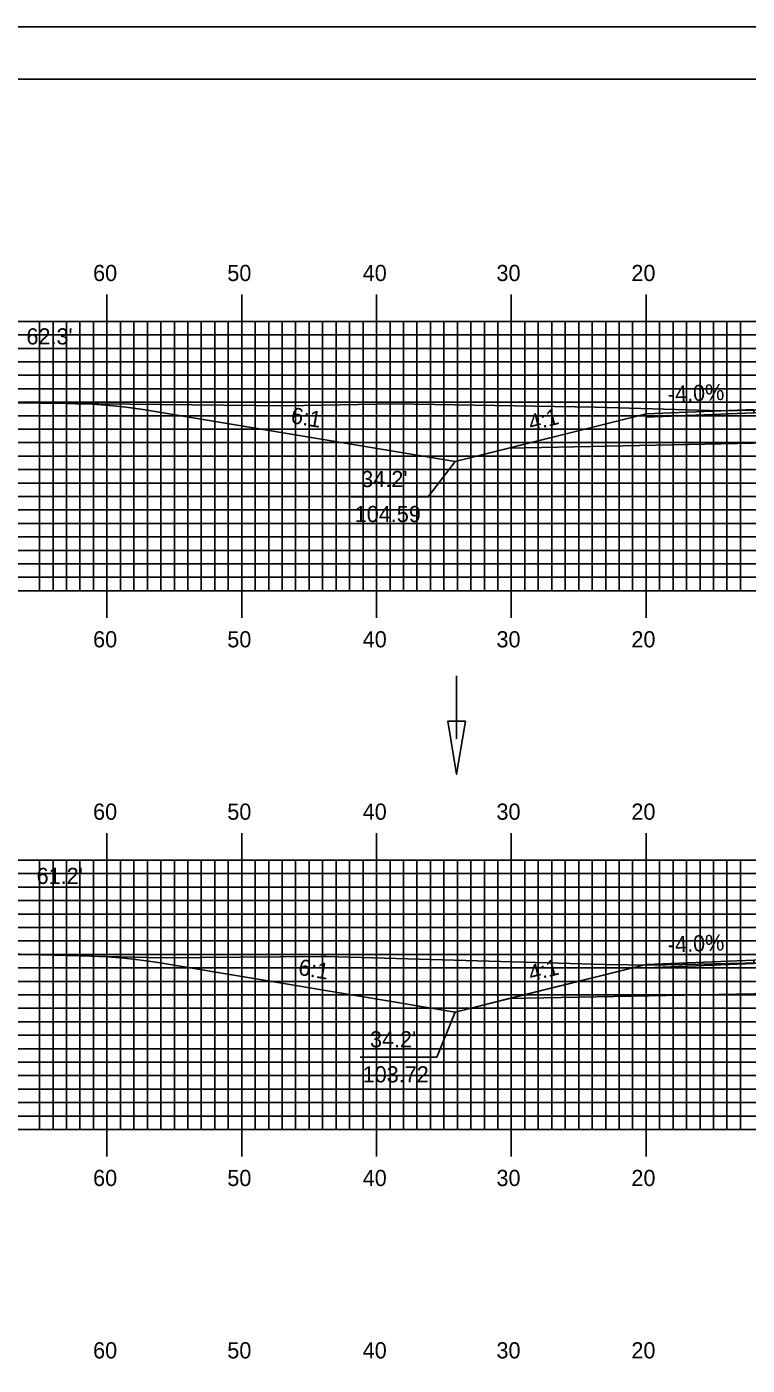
# Model space of a CAD drawing. Extents: x 1779106 to 1779449, y 442591 to 442811.
# Drawn here: x 1779205.4 to 1779258.8, y 442711.2 to 442810.5 of the extents above; entities that cross this region are included whole.
import ezdxf

# ---------------------------------------------------------------- set-up
doc = ezdxf.new("R2010")
doc.units = 0
for name, color, linetype in [('ANNOTATION', 7, 'Continuous'), ('BORDER', 7, 'Continuous'), ('D_Drainage_Ditch_Line', 7, 'Continuous'), ('D_Roadway_Centerline', 7, 'Continuous'), ('D_Roadway_Edge_Shoulder', 7, 'Continuous'), ('D_Roadway_SlopeLines', 7, 'Continuous'), ('D_Roadway_SubGrade', 7, 'Continuous'), ('D_Text_Standard', 7, 'Continuous'), ('H_V ANNOTATION', 7, 'Continuous'), ('MAJOR', 7, 'Continuous'), ('MINOR', 7, 'Continuous'), ('PLOT BOUNDARY', 7, 'Continuous'), ('S_Roadway_Centerline', 7, 'Continuous')]:
    doc.layers.add(name, color=color, linetype=linetype)

msp = doc.modelspace()

# ---------------------------------------------------------------- linework, layer by layer
at = {"layer": 'ANNOTATION'}
for points in [[(1779229.461, 442775.639), (1779235.153, 442775.639), (1779237.155, 442778.259)], [(1779230.108, 442734.035), (1779235.8, 442734.035), (1779237.155, 442737.384)]]:
    msp.add_lwpolyline(points, dxfattribs=at)
at = {"layer": 'BORDER'}
msp.add_lwpolyline([(1779121.729, 442596.665), (1779441.729, 442596.665), (1779441.729, 442806.665), (1779121.729, 442806.665)], close=True, dxfattribs=at)
at = {"layer": 'D_Drainage_Ditch_Line'}
msp.add_line((1779237.267, 442757.661), (1779237.267, 442762.36), dxfattribs=at)
msp.add_lwpolyline([(1779237.924, 442758.974), (1779236.611, 442758.974), (1779237.267, 442755.037)], close=True, dxfattribs=at)
at = {"layer": 'D_Roadway_Centerline'}
for points in [[(1779209.014, 442782.559), (1779210.264, 442782.521), (1779210.312, 442782.518), (1779211.513, 442782.435), (1779212.323, 442782.348), (1779212.764, 442782.3), (1779213.418, 442782.204), (1779214.014, 442782.116), (1779237.153, 442778.26), (1779237.155, 442778.259), (1779241.155, 442779.259), (1779251.329, 442781.802), (1779259.33, 442782.122)], [(1779210.128, 442741.537), (1779211.378, 442741.483), (1779212.589, 442741.387), (1779212.628, 442741.384), (1779212.654, 442741.381), (1779213.879, 442741.241), (1779215.128, 442741.055), (1779237.155, 442737.384), (1779241.156, 442738.384), (1779251.329, 442740.927), (1779259.329, 442741.247), (1779271.328, 442741.487), (1779271.329, 442741.487), (1779278.201, 442741.35), (1779283.329, 442741.247), (1779293.329, 442740.847), (1779303.329, 442738.348), (1779307.184, 442737.384)]]:
    msp.add_lwpolyline(points, dxfattribs=at)
at = {"layer": 'D_Roadway_Edge_Shoulder'}
for points in [[(1779259.33, 442782.122), (1779251.329, 442781.802), (1779251.329, 442781.552), (1779259.33, 442781.872)], [(1779259.329, 442741.247), (1779251.329, 442740.927), (1779251.329, 442740.677), (1779259.329, 442740.997)]]:
    msp.add_lwpolyline(points, close=True, dxfattribs=at)
at = {"layer": 'D_Roadway_SlopeLines'}
for points in [[(1779237.155, 442778.259), (1779214.014, 442782.116), (1779212.764, 442782.3), (1779211.513, 442782.435), (1779210.264, 442782.521), (1779209.014, 442782.559)], [(1779251.329, 442781.802), (1779237.155, 442778.259)], [(1779237.155, 442737.384), (1779215.128, 442741.055), (1779213.879, 442741.241), (1779212.628, 442741.384), (1779211.378, 442741.483), (1779210.128, 442741.537)], [(1779251.329, 442740.927), (1779237.155, 442737.384)]]:
    msp.add_lwpolyline(points, dxfattribs=at)
at = {"layer": 'D_Roadway_SubGrade'}
for points in [[(1779259.33, 442779.622), (1779241.155, 442779.259), (1779251.329, 442781.802), (1779251.329, 442781.552), (1779259.33, 442781.872), (1779271.329, 442782.112), (1779283.329, 442781.872), (1779291.329, 442781.552), (1779291.329, 442781.802), (1779301.503, 442779.259), (1779283.329, 442779.622), (1779271.329, 442779.862)], [(1779259.329, 442738.747), (1779241.156, 442738.384), (1779251.329, 442740.927), (1779251.329, 442740.677), (1779259.329, 442740.997), (1779271.329, 442741.237), (1779283.329, 442740.997), (1779293.329, 442740.597), (1779293.329, 442740.847), (1779303.329, 442738.348), (1779283.329, 442738.747), (1779271.329, 442738.987)]]:
    msp.add_lwpolyline(points, close=True, dxfattribs=at)
at = {"layer": 'MAJOR'}
for p, q in [((1779211.329, 442790.669), (1779211.329, 442788.665)), ((1779221.329, 442790.669), (1779221.329, 442788.665)), ((1779231.329, 442790.669), (1779231.329, 442788.665)), ((1779241.329, 442790.669), (1779241.329, 442788.665)), ((1779251.329, 442790.669), (1779251.329, 442788.665)), ((1779131.329, 442788.665), (1779411.329, 442788.665)), ((1779131.329, 442788.665), (1779411.329, 442788.665)), ((1779211.329, 442768.665), (1779211.329, 442788.665)), ((1779221.329, 442768.665), (1779221.329, 442788.665)), ((1779231.329, 442768.665), (1779231.329, 442788.665)), ((1779241.329, 442768.665), (1779241.329, 442788.665)), ((1779251.329, 442768.665), (1779251.329, 442788.665)), ((1779131.329, 442783.665), (1779411.329, 442783.665)), ((1779131.329, 442778.665), (1779411.329, 442778.665)), ((1779131.329, 442773.665), (1779411.329, 442773.665)), ((1779131.329, 442768.665), (1779411.329, 442768.665)), ((1779131.329, 442768.665), (1779411.329, 442768.665)), ((1779211.329, 442766.661), (1779211.329, 442768.665)), ((1779221.329, 442766.661), (1779221.329, 442768.665)), ((1779231.329, 442766.661), (1779231.329, 442768.665)), ((1779241.329, 442766.661), (1779241.329, 442768.665)), ((1779251.329, 442766.661), (1779251.329, 442768.665)), ((1779211.329, 442750.669), (1779211.329, 442748.665)), ((1779221.329, 442750.669), (1779221.329, 442748.665)), ((1779231.329, 442750.669), (1779231.329, 442748.665)), ((1779241.329, 442750.669), (1779241.329, 442748.665)), ((1779251.329, 442750.669), (1779251.329, 442748.665)), ((1779131.329, 442748.665), (1779411.329, 442748.665)), ((1779131.329, 442748.665), (1779411.329, 442748.665)), ((1779211.329, 442728.665), (1779211.329, 442748.665)), ((1779221.329, 442728.665), (1779221.329, 442748.665)), ((1779231.329, 442728.665), (1779231.329, 442748.665)), ((1779241.329, 442728.665), (1779241.329, 442748.665)), ((1779251.329, 442728.665), (1779251.329, 442748.665)), ((1779131.329, 442743.665), (1779411.329, 442743.665)), ((1779131.329, 442738.665), (1779411.329, 442738.665)), ((1779131.329, 442733.665), (1779411.329, 442733.665)), ((1779131.329, 442728.665), (1779411.329, 442728.665)), ((1779131.329, 442728.665), (1779411.329, 442728.665)), ((1779211.329, 442726.661), (1779211.329, 442728.665)), ((1779221.329, 442726.661), (1779221.329, 442728.665)), ((1779231.329, 442726.661), (1779231.329, 442728.665)), ((1779241.329, 442726.661), (1779241.329, 442728.665)), ((1779251.329, 442726.661), (1779251.329, 442728.665))]:
    msp.add_line(p, q, dxfattribs=at)
at = {"layer": 'MINOR'}
for p, q in [((1779206.329, 442768.665), (1779206.329, 442788.665)), ((1779207.329, 442768.665), (1779207.329, 442788.665)), ((1779208.329, 442768.665), (1779208.329, 442788.665)), ((1779209.329, 442768.665), (1779209.329, 442788.665)), ((1779210.329, 442768.665), (1779210.329, 442788.665)), ((1779212.329, 442768.665), (1779212.329, 442788.665)), ((1779213.329, 442768.665), (1779213.329, 442788.665)), ((1779214.329, 442768.665), (1779214.329, 442788.665)), ((1779215.329, 442768.665), (1779215.329, 442788.665)), ((1779216.329, 442768.665), (1779216.329, 442788.665)), ((1779217.329, 442768.665), (1779217.329, 442788.665)), ((1779218.329, 442768.665), (1779218.329, 442788.665)), ((1779219.329, 442768.665), (1779219.329, 442788.665)), ((1779220.329, 442768.665), (1779220.329, 442788.665)), ((1779222.329, 442768.665), (1779222.329, 442788.665)), ((1779223.329, 442768.665), (1779223.329, 442788.665)), ((1779224.329, 442768.665), (1779224.329, 442788.665)), ((1779225.329, 442768.665), (1779225.329, 442788.665)), ((1779226.329, 442768.665), (1779226.329, 442788.665)), ((1779227.329, 442768.665), (1779227.329, 442788.665)), ((1779228.329, 442768.665), (1779228.329, 442788.665)), ((1779229.329, 442768.665), (1779229.329, 442788.665)), ((1779230.329, 442768.665), (1779230.329, 442788.665)), ((1779232.329, 442768.665), (1779232.329, 442788.665)), ((1779233.329, 442768.665), (1779233.329, 442788.665)), ((1779234.329, 442768.665), (1779234.329, 442788.665)), ((1779235.329, 442768.665), (1779235.329, 442788.665)), ((1779236.329, 442768.665), (1779236.329, 442788.665)), ((1779237.329, 442768.665), (1779237.329, 442788.665)), ((1779238.329, 442768.665), (1779238.329, 442788.665)), ((1779239.329, 442768.665), (1779239.329, 442788.665)), ((1779240.329, 442768.665), (1779240.329, 442788.665)), ((1779242.329, 442768.665), (1779242.329, 442788.665)), ((1779243.329, 442768.665), (1779243.329, 442788.665)), ((1779244.329, 442768.665), (1779244.329, 442788.665)), ((1779245.329, 442768.665), (1779245.329, 442788.665)), ((1779246.329, 442768.665), (1779246.329, 442788.665)), ((1779247.329, 442768.665), (1779247.329, 442788.665)), ((1779248.329, 442768.665), (1779248.329, 442788.665)), ((1779249.329, 442768.665), (1779249.329, 442788.665)), ((1779250.329, 442768.665), (1779250.329, 442788.665)), ((1779252.329, 442768.665), (1779252.329, 442788.665)), ((1779253.329, 442768.665), (1779253.329, 442788.665)), ((1779254.329, 442768.665), (1779254.329, 442788.665)), ((1779255.329, 442768.665), (1779255.329, 442788.665)), ((1779256.329, 442768.665), (1779256.329, 442788.665)), ((1779257.329, 442768.665), (1779257.329, 442788.665)), ((1779258.329, 442768.665), (1779258.329, 442788.665)), ((1779131.329, 442787.665), (1779411.329, 442787.665)), ((1779131.329, 442786.665), (1779411.329, 442786.665)), ((1779131.329, 442785.665), (1779411.329, 442785.665)), ((1779131.329, 442784.665), (1779411.329, 442784.665)), ((1779131.329, 442782.665), (1779411.329, 442782.665)), ((1779131.329, 442781.665), (1779411.329, 442781.665)), ((1779131.329, 442780.665), (1779411.329, 442780.665)), ((1779131.329, 442779.665), (1779411.329, 442779.665)), ((1779131.329, 442777.665), (1779411.329, 442777.665)), ((1779131.329, 442776.665), (1779411.329, 442776.665)), ((1779131.329, 442775.665), (1779411.329, 442775.665)), ((1779131.329, 442774.665), (1779411.329, 442774.665)), ((1779131.329, 442772.665), (1779411.329, 442772.665)), ((1779131.329, 442771.665), (1779411.329, 442771.665)), ((1779131.329, 442770.665), (1779411.329, 442770.665)), ((1779131.329, 442769.665), (1779411.329, 442769.665)), ((1779206.329, 442728.665), (1779206.329, 442748.665)), ((1779207.329, 442728.665), (1779207.329, 442748.665)), ((1779208.329, 442728.665), (1779208.329, 442748.665)), ((1779209.329, 442728.665), (1779209.329, 442748.665)), ((1779210.329, 442728.665), (1779210.329, 442748.665)), ((1779212.329, 442728.665), (1779212.329, 442748.665)), ((1779213.329, 442728.665), (1779213.329, 442748.665)), ((1779214.329, 442728.665), (1779214.329, 442748.665)), ((1779215.329, 442728.665), (1779215.329, 442748.665)), ((1779216.329, 442728.665), (1779216.329, 442748.665)), ((1779217.329, 442728.665), (1779217.329, 442748.665)), ((1779218.329, 442728.665), (1779218.329, 442748.665)), ((1779219.329, 442728.665), (1779219.329, 442748.665)), ((1779220.329, 442728.665), (1779220.329, 442748.665)), ((1779222.329, 442728.665), (1779222.329, 442748.665)), ((1779223.329, 442728.665), (1779223.329, 442748.665)), ((1779224.329, 442728.665), (1779224.329, 442748.665)), ((1779225.329, 442728.665), (1779225.329, 442748.665)), ((1779226.329, 442728.665), (1779226.329, 442748.665)), ((1779227.329, 442728.665), (1779227.329, 442748.665)), ((1779228.329, 442728.665), (1779228.329, 442748.665)), ((1779229.329, 442728.665), (1779229.329, 442748.665)), ((1779230.329, 442728.665), (1779230.329, 442748.665)), ((1779232.329, 442728.665), (1779232.329, 442748.665)), ((1779233.329, 442728.665), (1779233.329, 442748.665)), ((1779234.329, 442728.665), (1779234.329, 442748.665)), ((1779235.329, 442728.665), (1779235.329, 442748.665)), ((1779236.329, 442728.665), (1779236.329, 442748.665)), ((1779237.329, 442728.665), (1779237.329, 442748.665)), ((1779238.329, 442728.665), (1779238.329, 442748.665)), ((1779239.329, 442728.665), (1779239.329, 442748.665)), ((1779240.329, 442728.665), (1779240.329, 442748.665)), ((1779242.329, 442728.665), (1779242.329, 442748.665)), ((1779243.329, 442728.665), (1779243.329, 442748.665)), ((1779244.329, 442728.665), (1779244.329, 442748.665)), ((1779245.329, 442728.665), (1779245.329, 442748.665)), ((1779246.329, 442728.665), (1779246.329, 442748.665)), ((1779247.329, 442728.665), (1779247.329, 442748.665)), ((1779248.329, 442728.665), (1779248.329, 442748.665)), ((1779249.329, 442728.665), (1779249.329, 442748.665)), ((1779250.329, 442728.665), (1779250.329, 442748.665)), ((1779252.329, 442728.665), (1779252.329, 442748.665)), ((1779253.329, 442728.665), (1779253.329, 442748.665)), ((1779254.329, 442728.665), (1779254.329, 442748.665)), ((1779255.329, 442728.665), (1779255.329, 442748.665)), ((1779256.329, 442728.665), (1779256.329, 442748.665)), ((1779257.329, 442728.665), (1779257.329, 442748.665)), ((1779258.329, 442728.665), (1779258.329, 442748.665)), ((1779131.329, 442747.665), (1779411.329, 442747.665)), ((1779131.329, 442746.665), (1779411.329, 442746.665)), ((1779131.329, 442745.665), (1779411.329, 442745.665)), ((1779131.329, 442744.665), (1779411.329, 442744.665)), ((1779131.329, 442742.665), (1779411.329, 442742.665)), ((1779131.329, 442741.665), (1779411.329, 442741.665)), ((1779131.329, 442740.665), (1779411.329, 442740.665)), ((1779131.329, 442739.665), (1779411.329, 442739.665)), ((1779131.329, 442737.665), (1779411.329, 442737.665)), ((1779131.329, 442736.665), (1779411.329, 442736.665)), ((1779131.329, 442735.665), (1779411.329, 442735.665)), ((1779131.329, 442734.665), (1779411.329, 442734.665)), ((1779131.329, 442732.665), (1779411.329, 442732.665)), ((1779131.329, 442731.665), (1779411.329, 442731.665)), ((1779131.329, 442730.665), (1779411.329, 442730.665)), ((1779131.329, 442729.665), (1779411.329, 442729.665))]:
    msp.add_line(p, q, dxfattribs=at)
at = {"layer": 'PLOT BOUNDARY'}
msp.add_lwpolyline([(1779105.542, 442590.547), (1779445.542, 442590.547), (1779445.542, 442810.547), (1779105.542, 442810.547)], close=True, dxfattribs=at)
at = {"layer": 'S_Roadway_Centerline'}
for points in [[(1779204.323, 442782.626), (1779208.379, 442782.565), (1779224.594, 442782.397), (1779232.647, 442782.554), (1779247.552, 442782.307), (1779256.889, 442782.027), (1779269.461, 442782.27), (1779279.535, 442782.073), (1779285.297, 442781.72), (1779290.781, 442781.564), (1779304.666, 442781.605), (1779309.156, 442781.709), (1779314.679, 442781.638), (1779321.178, 442781.598), (1779327.747, 442781.551), (1779336.863, 442781.816)], [(1779203.403, 442741.748), (1779205.429, 442741.661), (1779215.254, 442741.403), (1779227.205, 442741.499), (1779227.424, 442741.508), (1779227.624, 442741.505), (1779248.292, 442740.919), (1779251.636, 442740.867), (1779261.056, 442741.059), (1779270.858, 442740.865), (1779273.556, 442740.862), (1779276.254, 442740.833), (1779285.251, 442740.863), (1779294.223, 442740.845), (1779299.806, 442740.668), (1779307.59, 442740.221), (1779317.29, 442740.535), (1779320.153, 442740.619), (1779322.749, 442740.624), (1779342.777, 442739.919)]]:
    msp.add_lwpolyline(points, dxfattribs=at)

# ---------------------------------------------------------------- texts
at = {"layer": 'ANNOTATION'}
for s, rotation, p in [('-4.0%', 2.29053, (1779252.961, 442782.669)), ('6:1', 350.53748, (1779224.917, 442781.127)), ('4:1', 14.03404, (1779242.778, 442780.526)), ('-4.0%', 2.29053, (1779252.961, 442741.794)), ('6:1', 350.538, (1779225.475, 442740.158)), ('4:1', 14.03473, (1779242.778, 442739.651))]:
    msp.add_text(s, height=1.2, rotation=rotation, dxfattribs=at).set_placement(p)
for s, p in [("34.2'", (1779230.196, 442776.365)), ('104.59', (1779229.709, 442773.765)), ("34.2'", (1779230.843, 442734.761)), ('103.72', (1779230.297, 442732.161))]:
    msp.add_text(s, height=1.2, dxfattribs=at).set_placement(p)
at = {"layer": 'D_Text_Standard'}
for s, p in [("62.3'", (1779205.355, 442786.956)), ("61.2'", (1779206.11, 442746.895))]:
    msp.add_text(s, height=1.2, dxfattribs=at).set_placement(p)
at = {"layer": 'H_V ANNOTATION'}
for s, p in [('60', (1779210.301, 442791.665)), ('50', (1779220.258, 442791.665)), ('40', (1779230.301, 442791.665)), ('30', (1779240.227, 442791.665)), ('20', (1779250.237, 442791.665)), ('60', (1779210.301, 442764.465)), ('50', (1779220.258, 442764.465)), ('40', (1779230.301, 442764.465)), ('30', (1779240.227, 442764.465)), ('20', (1779250.237, 442764.465)), ('60', (1779210.301, 442751.665)), ('50', (1779220.258, 442751.665)), ('40', (1779230.301, 442751.665)), ('30', (1779240.227, 442751.665)), ('20', (1779250.237, 442751.665)), ('60', (1779210.301, 442724.465)), ('50', (1779220.258, 442724.465)), ('40', (1779230.301, 442724.465)), ('30', (1779240.227, 442724.465)), ('20', (1779250.237, 442724.465)), ('60', (1779210.301, 442711.665)), ('50', (1779220.258, 442711.665)), ('40', (1779230.301, 442711.665)), ('30', (1779240.227, 442711.665)), ('20', (1779250.237, 442711.665))]:
    msp.add_text(s, height=1.2, dxfattribs=at).set_placement(p)

doc.saveas('drawing.dxf')
